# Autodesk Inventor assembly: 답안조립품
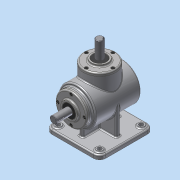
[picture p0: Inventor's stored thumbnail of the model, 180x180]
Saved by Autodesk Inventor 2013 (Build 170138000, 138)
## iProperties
Created: 2015-07
Part Number: 답안조립품
Document SubType Name: Assembly
Designer: Administrator
Author: Administrator
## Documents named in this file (14)
- C:\Users\Administrator\Desktop\450706V1008\답안조립품.iam
- C:\Users\Administrator\Desktop\450706V1008\본체.ipt
- C:\Users\Administrator\Desktop\450706V1008\M4.ipt
- C:\Users\Administrator\Desktop\450706V1008\메인 베벨기어.ipt
- C:\Users\Administrator\Desktop\450706V1008\메인 축.ipt
- 메인 축.ipt
- C:\Users\Administrator\Desktop\450706V1008\베어링 6203.ipt
- C:\Users\Administrator\Desktop\450706V1008\서브 베벨기어.ipt
- C:\Users\Administrator\Desktop\450706V1008\서브 축.ipt
- 서브 축.ipt
- C:\Users\Administrator\Desktop\450706V1008\오일실.ipt
- C:\Users\Administrator\Desktop\450706V1008\커버.ipt
- C:\Users\Administrator\Desktop\450706V1008\키 4x4.ipt
- C:\Users\Administrator\Desktop\450706V1008\키 5x5.ipt
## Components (8 placed, 1 different names)
1. M4:1
2. M4:3
3. M4:4
4. M4:5
5. M4:2
6. M4:6
7. M4:7
8. M4:8
